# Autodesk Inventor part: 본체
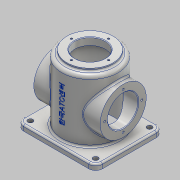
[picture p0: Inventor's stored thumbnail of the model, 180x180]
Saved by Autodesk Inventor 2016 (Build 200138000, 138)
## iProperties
Created: 2021-02
Part Number: 본체
Material: 알루미늄 6061
Document SubType Name: Modeling
Designer: user
Density: 2.7 g/cm^3
Appearance: 알루미늄 - 평지
Mass: 1235.14 g
Surface Area: 1068.45 cm^2
Volume: 457.459 cm^3
Author: user
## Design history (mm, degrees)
sketch "스케치1"
  geometry: L1 (-70, 60)-(70, 60); L2 (70, 60)-(70, -60); L3 (70, -60)-(-70, -60); L4 (-70, -60)-(-70, 60); L5 (-70, 60)-(70, -60); L6 (70, 60)-(-70, -60); 1 further point
  constraints: 12 end point, 2 midpoint, 2 parallel, 1 horizontal, 1 perpendicular
  dimensions: "d0" = 140 distance of L2.end L3.end; "d1" = 120 distance of L1.end L2.end
extrude "돌출1" new body sketch "스케치1" distance "d2" = 10; taper "d3" = 0 deg
fillet "모깎기1" dims "d4" = 12
hole "구멍1" diameter "d7" = 9; stored, may be unused: countersink angle "d11" = 90 deg, drill point angle "d13" = 118 deg; dims "d5" = 10, "d6" = 10, "d8" = 6, "d9" = 4, "d10" = 2, "d12" = 8
sketch "스케치2"
  geometry: C1 r 50 at (0, 0); 1 further point
  constraints: 1 centre point, 1 coincident
  dimensions: "d20" = 100 diameter of C1
extrude "돌출2" join sketch "스케치2" distance "d21" = 110; taper "d22" = 0 deg
sketch "스케치3"
  geometry: C1 r 41 at (0, 0); 1 further point
  constraints: 1 centre point, 1 coincident
  dimensions: "d23" = 82 diameter of C1
extrude "돌출3" join sketch "스케치3" distance "d24" = 5; taper "d25" = 0 deg
sketch "스케치5"
  geometry: 2 further points
  constraints: 1 coincident
hole "구멍2" sketch "스케치5" at (0, 0) diameter "d27" = 54; stored, may be unused: countersink angle "d31" = 90 deg, drill point angle "d33" = 118 deg; dims "d28" = 6, "d29" = 84, "d30" = 112, "d32" = 125
node "작업 평면1"
sketch "스케치6"
  geometry: L1 (50, 120)-(-50, 120) reference; L2 (-50, 10)-(50, 10) reference; L3 (48, 0)-(-48, 0) reference; L4 (48, 10)-(48, 0) reference; L5 (-48, 10)-(48, 10) reference; L6 (-48, 0)-(-48, 10) reference; L7 (48, 0)-(-48, 0) reference; C1 r 41 at (0, 60); 2 further points
  constraints: 1 centre point, 1 midpoint, 1 vertical alignment
  dimensions: "d35" = 82 diameter of C1; "d36" = 60 distance from line of C1.centre L3
extrude "돌출4" join sketch "스케치6" stored distance "d37" = 5; taper "d38" = 0 deg
hole "구멍3" diameter "d41" = 54; stored, may be unused: countersink angle "d45" = 90 deg, drill point angle "d47" = 118 deg; dims "d39" = 10, "d40" = 10, "d42" = 6, "d43" = 84, "d44" = 112, "d46" = 125
chamfer "모따기1" distance "d48" = 1; stored, may be unused: second distance "d49" = 2, angle "d50" = 45 deg
chamfer "모따기2" distance "d51" = 1; stored, may be unused: second distance "d52" = 2, angle "d53" = 45 deg
sketch "스케치7"
  geometry: L1 (-60, -48)-(-60, 48) reference; L2 (0, 0)-(33, 0); C1 r 41 at (0, 0) reference; C2 r 28 at (0, 0) reference; 1 further point
  constraints: 2 end point, 1 horizontal
  dimensions: "d54" = 33 distance of L2.start L2.end
hole "구멍4" sketch "스케치7" at (33, 0) diameter "d55" = 3.459; stored, may be unused: countersink angle "d59" = 90 deg, drill point angle "d61" = 118 deg; dims "d56" = 8, "d57" = 84, "d58" = 112, "d60" = 10
fillet "모깎기2" dims "d65" = 6
fillet "모깎기3" dims "d66" = 3
fillet "모깎기4" dims "d67" = 3
fillet "모깎기5" dims "d68" = 3
fillet "모깎기6" dims "d69" = 3
fillet "모깎기7" dims "d70" = 3
sketch "스케치8"
  geometry: L1 (0, 0)-(33, 0); C1 r 41 at (0, 0) reference; C2 r 28 at (0, 0) reference; 1 further point
  constraints: 2 end point, 1 horizontal
  dimensions: "d71" = 33 distance of L1.start L1.end
hole "구멍5" sketch "스케치8" at (33, 0) diameter "d72" = 3.459; stored, may be unused: countersink angle "d76" = 90 deg, drill point angle "d78" = 118 deg; dims "d73" = 8, "d74" = 84, "d75" = 112, "d77" = 10
node "작업 평면3"
sketch "스케치9"
  geometry: L1 (58, 0)-(-58, 0) reference; 3 further points
  constraints: 1 midpoint, 1 vertical alignment, 1 other
  dimensions: "d83" = 66 distance from line of point (0, 66) L1
feature "엠보싱1" sketch "스케치9" dims "d0" = 140, "d1" = 120, "d84" = 0.5, "d85" = 0
node "솔리드1"
pattern_linear "직사각형 패턴1" dims "d16" = 116, "d19" = 96
mirror "대칭1"
pattern_circular "원형 패턴1" dims angle "d63" = 360 deg
mirror "대칭2"
pattern_circular "원형 패턴2" dims angle "d80" = 360 deg
node "투영된 루프1"
node "투영된 루프2"
node "작업 평면2"
node "투영된 루프3"
node "투영된 루프4"
other parameters: "d34" = 59
